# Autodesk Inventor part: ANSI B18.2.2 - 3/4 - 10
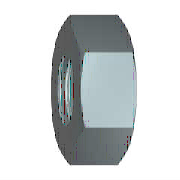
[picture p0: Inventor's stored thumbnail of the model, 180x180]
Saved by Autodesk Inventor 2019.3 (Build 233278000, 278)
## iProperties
Created: 2018-01
Part Number: ANSI B18.2.2 - 3/4 - 10
Material: Steel, Mild
Description: Hex Nuts (Inch Series) Heavy Hex Nut
Document SubType Name: Modeling
Standard: ANSI B18.2.2
Designer: u1426
Standard Revision: 2010
Standards Organization: ANSI
Language: en-US
Size Designation: 3/4 - 10
Categories: <MemberInstance><Categories><Category DisplayName="Fasteners" InternalName="e4da775c-781d-43d5-af7c-5136215cf5a6" Mnemonic="FSTN"><Category DisplayName="Nuts" I
Density: 7.85 g/cm^3
Appearance: Semi-Polished
IsCustomPart: 0
Author: u1426
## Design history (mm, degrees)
sketch "Sketch1"
  geometry: L1 (-18.331, 0)-(-9.165, 15.875); L2 (-9.165, 15.875)-(9.165, 15.875); L3 (9.165, 15.875)-(18.331, 0); L4 (18.331, 0)-(9.165, -15.875); L5 (9.165, -15.875)-(-9.165, -15.875); L6 (-9.165, -15.875)-(-18.331, 0); 2 further points
  constraints: 12 end point, 1 coincident, 1 horizontal, 11 other
  dimensions: "d0" = 36.66174 distance of L3.end L1.start (= 1.1547 x SW)
extrude "Body" new body sketch "Sketch1" distance "d1" = 18.6436 (= KOH); taper "d2" = 0 deg
sketch "Sketch2"
  geometry: L1 (0, 9.165)-(0, 18.331) reference; L2 (0, 18.331)-(18.644, 18.331) reference; L3 (18.644, 9.165)-(18.644, 18.331) reference; L4 (-3.729, 0)-(22.372, 0) reference; L5 (1.145, 18.331)-(0, 15.875); L6 (17.498, 18.331)-(18.644, 15.875)
  constraints: 4 end point, 4 point on line
  dimensions: "d3" = 25 deg angle of L1 L5 (= ANG1); "d4" = 25 deg angle of L3 L6 (= ANG2); "d5" = 31.75 diameter of L5.end L4 (= SW0); "d6" = 31.75 diameter of L6.end L4 (= SW01)
revolve "Chamfer1" sketch "Sketch2" stored, may be unused: angle "d7" = 90 deg
sketch "Sketch3"
  geometry: A1 r 15.875 centre (0, 0) between (-7.937, -13.748) and (7.938, -13.748) reference; 1 further point
  constraints: 1 coincident
hole "Thread" sketch "Sketch3" at (0, 0) diameter "d25" = 16.3068; stored, may be unused: countersink angle "d29" = 82 deg, drill point angle "d31" = 118 deg; dims "d26" = 6, "d27" = 4, "d28" = 2, "d30" = 8
workaxis "Work Axis1"
workplane "Work Plane1"
body "Solid1"
chamfer "Chamfer2" distance "d8" = 1.37482 (= -0.5 x GD1 + 0.5 x NND); stored, may be unused: angle "d9" = 30 deg, second distance "d40" = 1.37482 (= -0.5 x GD1 + 0.5 x NND)
chamfer "Chamfer3" distance "d10" = 1.37482 (= -0.5 x GD1 + 0.5 x NND); stored, may be unused: angle "d11" = 30 deg, second distance "d41" = 1.37482 (= -0.5 x GD1 + 0.5 x NND)
other parameters: "ANG1" = 25 deg [user parameter; used in 1 equation term], "ANG2" = 25 deg [user parameter; used in 1 equation term], "NND" = 19.05 [user parameter; used in 4 equation terms], "KOH" = 18.6436 [user parameter; used in 1 equation term], "SW" = 31.75 [user parameter; used in 4 equation terms], "SW0" = 31.75 (= SW) [user parameter; used in 1 equation term], "SW01" = 31.75 (= SW) [user parameter; used in 1 equation term], "GD1" = 16.30037 (computed from THREADDIA, PTC, TOA) [user parameter; used in 4 equation terms], "d13" = 0, "d14" = 0, "d39" = 0, "d42" = 0, "THREADDIA" = 19.05 [user parameter; used in 1 equation term], "TOA" = 30 deg [user parameter; used in 1 equation term], "PTC" = 2.54 (computed from TPU) [user parameter; used in 1 equation term], "E0" = 36.67125 (= 1.155 x SW) [user parameter]
